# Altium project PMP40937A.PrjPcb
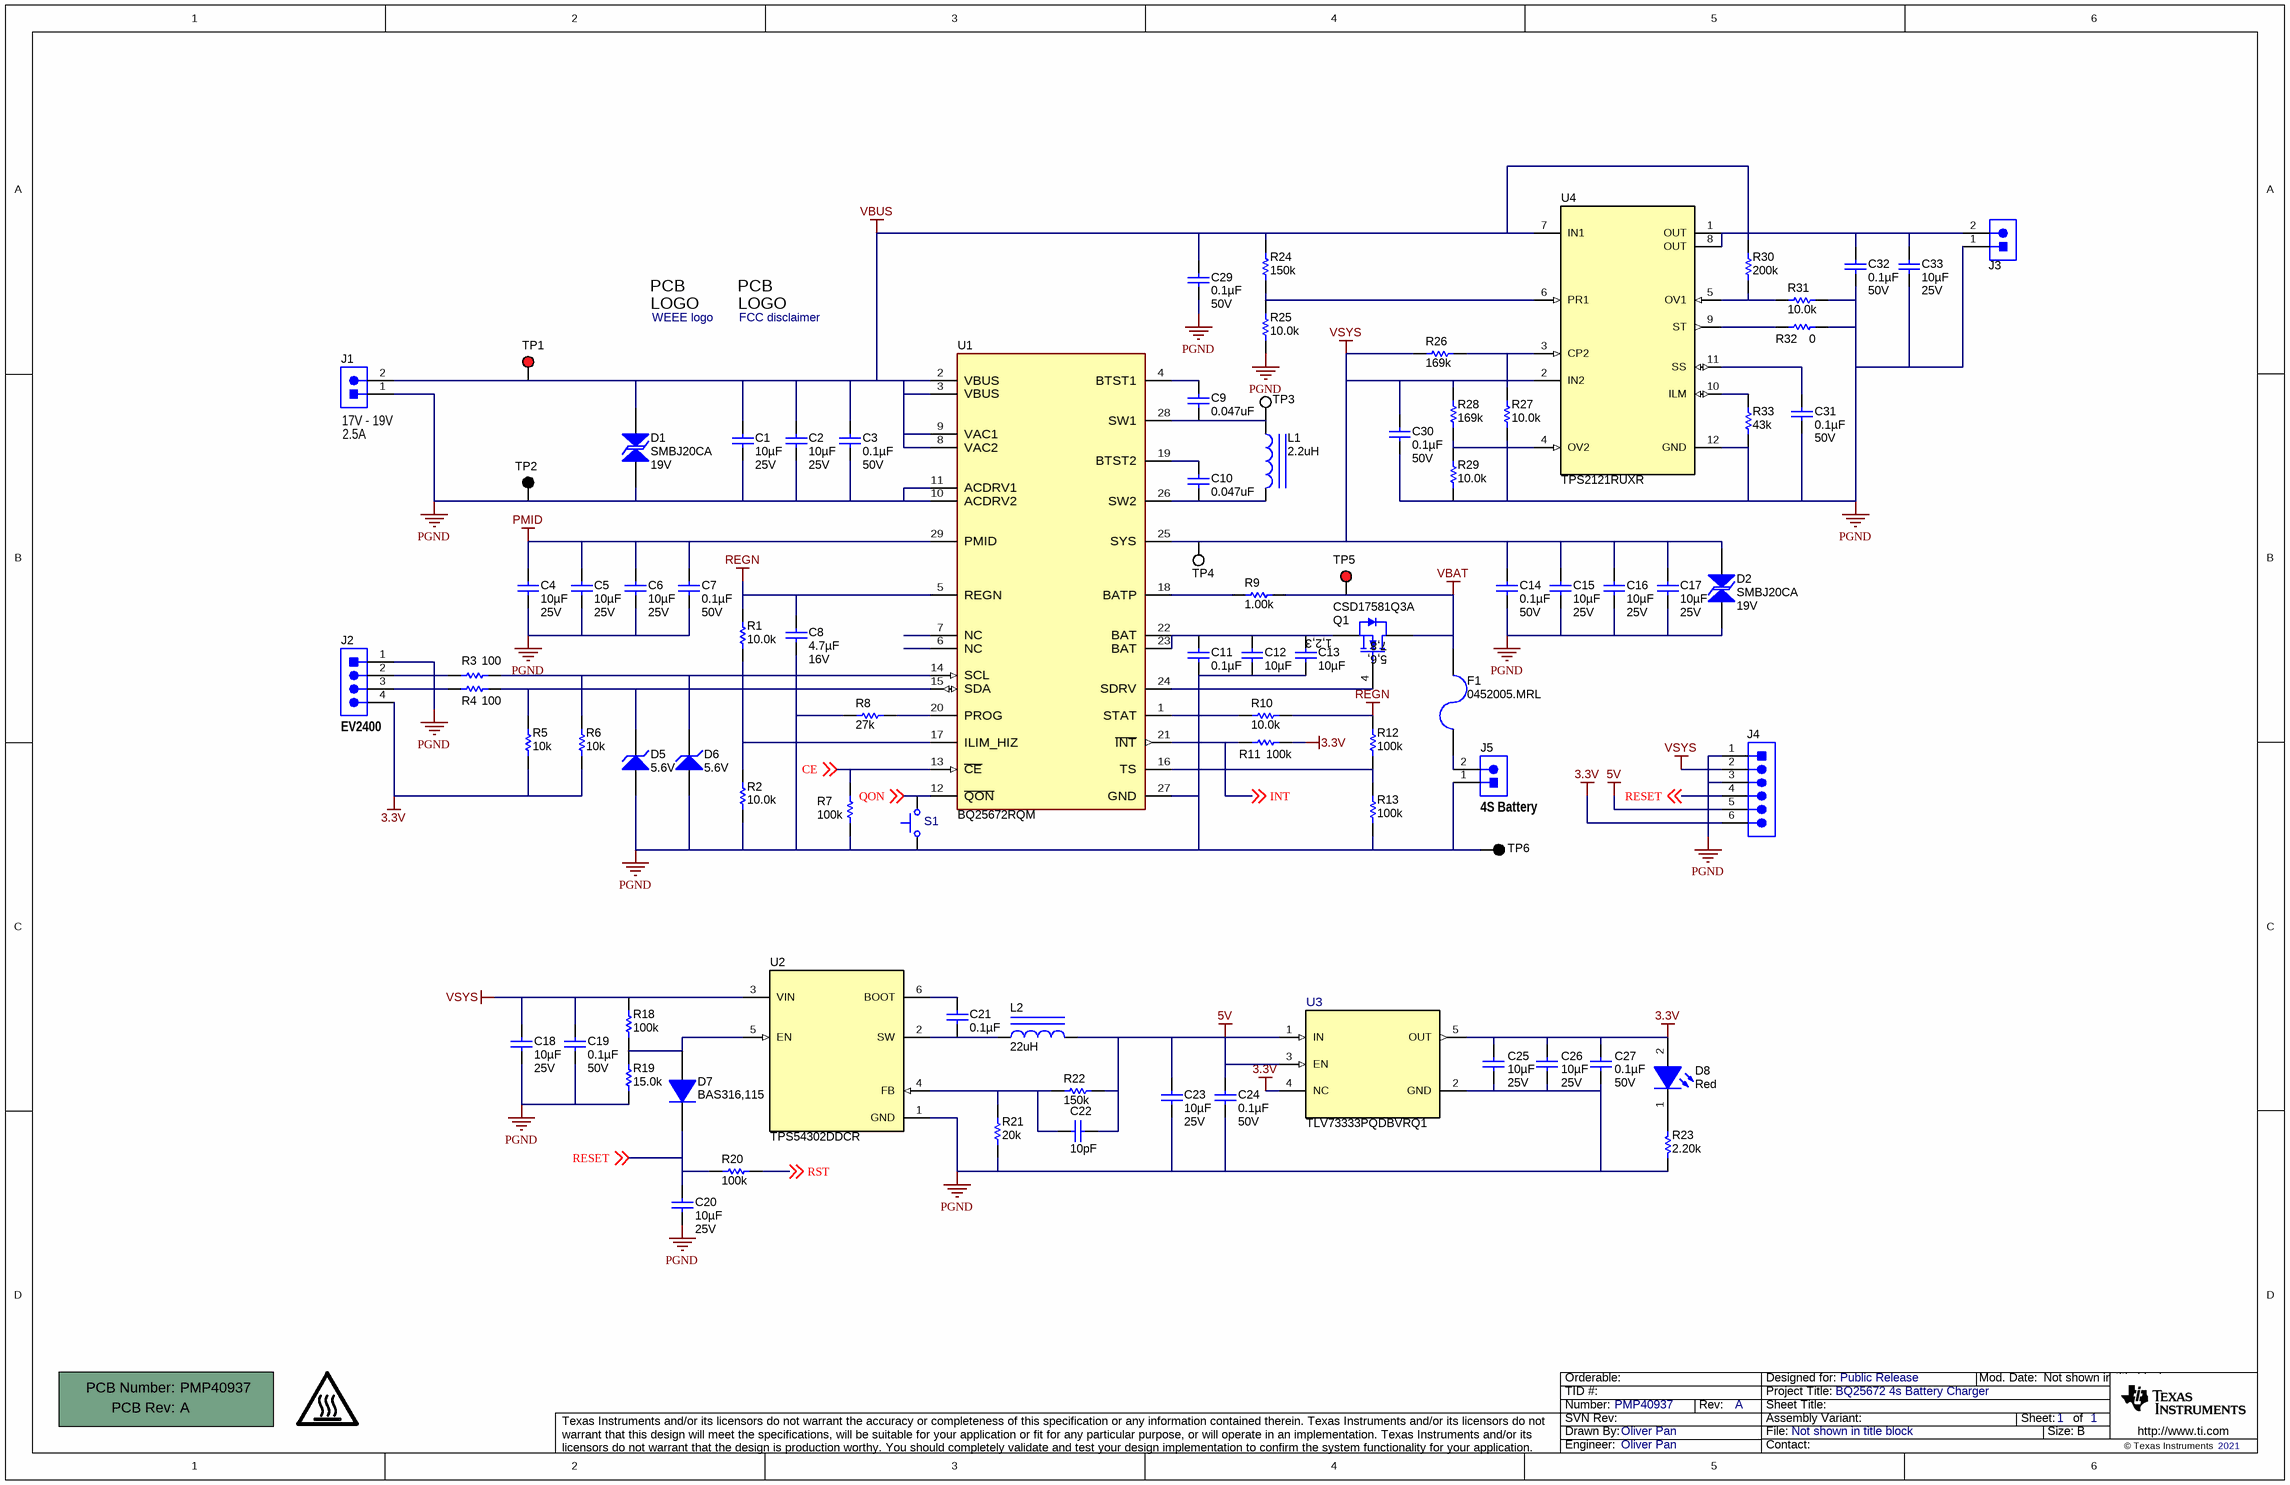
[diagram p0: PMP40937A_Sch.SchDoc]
A: http://www.ti.com/support; CopyrightYear: 2021; PCB_Layout: Oliver Pan; PCB_Rev: A; PRJ_Customer: Public Release; PRJ_Engineer: Oliver Pan; PRJ_Number: PMP40937; PRJ_Title: BQ25672 4s Battery Charger; SCH_Rev: A
1 sheet, 91 parts. Net scope: global (net labels, ports and power ports of the same name join across sheets).
Board file: PMP40937A_PCB.PcbDoc

## Sheet PMP40937A_Sch.SchDoc
size 431 x 279 mm; Date: Not shown in title block; ApprovedBy: Not shown in title block; CheckedBy: Not shown in title block; Author: Not shown in title block; CompanyName: Not shown in title block; DrawnBy: Oliver Pan; Engineer: Not shown in title block; Organization: Not shown in title block; Address1: Not shown in title block; Address2: Not shown in title block; Address3: Not shown in title block; Address4: Not shown in title block; Revision: Use project parameter SCH_Rev; PageSetup: Record=PageOptions¦CenterHorizontal=True¦CenterVertical=True¦PrintScale=1.00¦XCorrection=1.00¦YCorrection=1.00¦PrintKind=0¦BorderSize=5000000¦LeftOffset=0¦BottomOffset=0¦Orientation=2¦PaperLength=1000¦PaperWidth=1000¦Scale=100¦PaperSource=15¦PrintQuality=600¦MediaType=1¦DitherType=10¦PaperKind=Letter¦PrintScaleMode=1; DocumentNumber: 1; SheetNumber: 1; SheetTotal: 1

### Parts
!PCB1  Printed Circuit Board  (value not drawn)  (mechanical)
C1  ValueDisplayed: 10µF  Value2: 25V  [0805]  (hidden comment: CL21A106KAFN3NE)
C2  ValueDisplayed: 10µF  Value2: 25V  [0805]  (hidden comment: CL21A106KAFN3NE)
C3  ValueDisplayed: 0.1µF  Value2: 50V  [0402L]  (hidden comment: GRM155R71H104ME14D)
C4  ValueDisplayed: 10µF  Value2: 25V  [0805]  (hidden comment: CL21A106KAFN3NE)
C5  ValueDisplayed: 10µF  Value2: 25V  [0805]  (hidden comment: CL21A106KAFN3NE)
C6  ValueDisplayed: 10µF  Value2: 25V  [0805]  (hidden comment: CL21A106KAFN3NE)
C7  ValueDisplayed: 0.1µF  Value2: 50V  [0402L]  (hidden comment: GRM155R71H104ME14D)
C8  ValueDisplayed: 4.7µF  Value2: 16V  [0603L]  (hidden comment: GRM188R61C475KAAJ)
C9  ValueDisplayed: 0.047uF  [0402L]  (hidden comment: GRM155R71E473KA88D)
C10  ValueDisplayed: 0.047uF  [0402L]  (hidden comment: GRM155R71E473KA88D)
C11  ValueDisplayed: 0.1µF  [0402L]  (hidden comment: GRM155R71H104ME14D)
C12  ValueDisplayed: 10µF  [0805]  (hidden comment: CL21A106KAFN3NE)
C13  ValueDisplayed: 10µF  [0805]  (hidden comment: CL21A106KAFN3NE)
C14  ValueDisplayed: 0.1µF  Value2: 50V  [0402L]  (hidden comment: GRM155R71H104ME14D)
C15  ValueDisplayed: 10µF  Value2: 25V  [0805]  (hidden comment: CL21A106KAFN3NE)
C16  ValueDisplayed: 10µF  Value2: 25V  [0805]  (hidden comment: CL21A106KAFN3NE)
C17  ValueDisplayed: 10µF  Value2: 25V  [0805]  (hidden comment: CL21A106KAFN3NE)
C18  ValueDisplayed: 10µF  Value2: 25V  [0603L]  (hidden comment: GRM188R61E106MA73D)
C19  ValueDisplayed: 0.1µF  Value2: 50V  [0402L]  (hidden comment: GRM155R71H104ME14D)
C20  ValueDisplayed: 10µF  Value2: 25V  [0603L]  (hidden comment: GRM188R61E106MA73D)
C21  ValueDisplayed: 0.1µF  [0402L]  (hidden comment: GRM155R71H104ME14D)
C22  ValueDisplayed: 10pF  [0402L]  (hidden comment: GRM1555C1H100FA01D)
C23  ValueDisplayed: 10µF  Value2: 25V  [0603L]  (hidden comment: GRM188R61E106MA73D)
C24  ValueDisplayed: 0.1µF  Value2: 50V  [0402L]  (hidden comment: GRM155R71H104ME14D)
C25  ValueDisplayed: 10µF  Value2: 25V  [0603L]  (hidden comment: GRM188R61E106MA73D)
C26  ValueDisplayed: 10µF  Value2: 25V  [0603L]  (hidden comment: GRM188R61E106MA73D)
C27  ValueDisplayed: 0.1µF  Value2: 50V  [0402L]  (hidden comment: GRM155R71H104ME14D)
C29  ValueDisplayed: 0.1µF  Value2: 50V  [0402L]  (hidden comment: GRM155R71H104ME14D)
C30  ValueDisplayed: 0.1µF  Value2: 50V  [0402L]  (hidden comment: GRM155R71H104ME14D)
C31  ValueDisplayed: 0.1µF  Value2: 50V  [0402L]  (hidden comment: GRM155R71H104ME14D)
C32  ValueDisplayed: 0.1µF  Value2: 50V  [0402L]  (hidden comment: GRM155R71H104ME14D)
C33  ValueDisplayed: 10µF  Value2: 25V  [0805]  (hidden comment: CL21A106KAFN3NE)
D1  SMBJ20CA  value 19V  [SMB]
D2  SMBJ20CA  value 19V  [SMB]
D5  value 5.6V  [SOD-523]  (hidden comment: BZT52C5V6T-7)
D6  value 5.6V  [SOD-523]  (hidden comment: BZT52C5V6T-7)
D7  BAS316,115  [SOD-323]
D8  value Red  [WL-SMCW_RED]  (hidden comment: 150060RS75000)
F1  0452005.MRL  [SloBlo452]
J1  B2B-XH-A(LF)(SN)  [JST_B2B-XH-A]  (value not drawn)
J2  61300411121  [WURTH_61300411121]  (value not drawn)
J3  B2B-XH-A(LF)(SN)  [JST_B2B-XH-A]  (value not drawn)
J4  61300611121  [WURTH_61300611121]  (value not drawn)
J5  B2B-XH-A(LF)(SN)  [JST_B2B-XH-A]  (value not drawn)
L1  ValueDisplayed: 2.2uH  [SPM6530]  (hidden comment: SPM6530T-2R2M)
L2  ValueDisplayed: 22uH  [WE-LHMI_7030]  (hidden comment: 74437346220)
Logo1  WEEE logo  [WEEE_Minimum]  (no BOM)
Logo2  FCC disclaimer  [FCC_disclaimer]  (no BOM)
LOGO3  CAUTION HOT SURFACE  [IEC_HotSurface_Small]  (value not drawn)  (no BOM)
Q1  CSD17581Q3A  [DNH0008A]
R1  ValueDisplayed: 10.0k  [0402L]  (hidden comment: CRCW040210K0FKED)
R2  ValueDisplayed: 10.0k  [0402L]  (hidden comment: CRCW040210K0FKED)
R3  ValueDisplayed: 100  [0402L]  (hidden comment: RC0402FR-07100RL)
R4  ValueDisplayed: 100  [0402L]  (hidden comment: RC0402FR-07100RL)
R5  ValueDisplayed: 10k  [0402L]  (hidden comment: CRCW040210K0JNED)
R6  ValueDisplayed: 10k  [0402L]  (hidden comment: CRCW040210K0JNED)
R7  ValueDisplayed: 100k  [0402L]  (hidden comment: RC0402FR-07100KL)
R8  ValueDisplayed: 27k  [0402L]  (hidden comment: CRCW040227K0JNED)
R9  ValueDisplayed: 1.00k  [0402L]  (hidden comment: RC0402FR-071KL)
R10  ValueDisplayed: 10.0k  [0402L]  (hidden comment: CRCW040210K0FKED)
R11  ValueDisplayed: 100k  [0402L]  (hidden comment: RC0402FR-07100KL)
R12  ValueDisplayed: 100k  [0402L]  (hidden comment: CRCW0402100KFKED)
R13  ValueDisplayed: 100k  [0402L]  (hidden comment: CRCW0402100KFKED)
R18  ValueDisplayed: 100k  [0402L]  (hidden comment: CRCW0402100KFKED)
R19  ValueDisplayed: 15.0k  [0402L]  (hidden comment: CRCW040215K0FKED)
R20  ValueDisplayed: 100k  [0402L]  (hidden comment: RC0402FR-07100KL)
R21  ValueDisplayed: 20k  [0402L]  (hidden comment: CRCW040220K0JNED)
R22  ValueDisplayed: 150k  [0402L]  (hidden comment: CRCW0402150KFKED)
R23  ValueDisplayed: 2.20k  [0402L]  (hidden comment: RC0402FR-072K2L)
R24  ValueDisplayed: 150k  [0402L]  (hidden comment: CRCW0402150KFKED)
R25  ValueDisplayed: 10.0k  [0402L]  (hidden comment: CRCW040210K0FKED)
R26  ValueDisplayed: 169k  [0402L]  (hidden comment: CRCW0402169KFKED)
R27  ValueDisplayed: 10.0k  [0402L]  (hidden comment: CRCW040210K0FKED)
R28  ValueDisplayed: 169k  [0402L]  (hidden comment: CRCW0402169KFKED)
R29  ValueDisplayed: 10.0k  [0402L]  (hidden comment: CRCW040210K0FKED)
R30  ValueDisplayed: 200k  [0402L]  (hidden comment: CRCW0402200KFKED)
R31  ValueDisplayed: 10.0k  [0402L]  (hidden comment: CRCW040210K0FKED)
R32  ValueDisplayed: 0  [0402L]  (hidden comment: CRCW04020000Z0ED)
R33  ValueDisplayed: 43k  [0402L]  (hidden comment: CRCW040243K0JNED)
S1  B3U-1100P  [SW_B3U-1000P]  (value not drawn)
TP1  5010  [Keystone5010]  (value not drawn)
TP2  5011  [Keystone5011]  (value not drawn)
TP3  5002  [Keystone5002]  (value not drawn)
TP4  5002  [Keystone5002]  (value not drawn)
TP5  5000  [Keystone5000]  (value not drawn)
TP6  5011  [Keystone5011]  (value not drawn)
U1  BQ25672RQM  [RQM0029A-MFG]
U2  TPS54302DDCR  [DDC0006A_N]
U3  TLV73333PQDBVRQ1  [DBV0005A_N]
U4  TPS2121RUXR  [RUX0012A]

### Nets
3.3V: C25.1 C26.1 C27.2 D8.2(A) J2.4 J4.6 R5.1 R6.1 R11.1 U3.4(NC) U3.5(OUT)
5V: C22.1 C23.1 C24.2 J4.5 L2.2 R22.1 U3.1(IN) U3.3(EN)
PGND: C1.2 C2.2 C3.1 C4.2 C5.2 C6.2 C7.1 C8.1 C11.1 C12.2 C13.2 C14.1 C15.2 C16.2 C17.2 C18.2 C19.1 C20.2 C23.2 C24.1 C25.2 C26.2 C27.1 C29.1 C30.1 C31.1 C32.1 C33.2 D1.2 D2.2 D5.2(A) D6.2(A) J1.1 J2.1 J3.1 J4.1 J4.3 J5.1 R2.1 R7.2 R8.2 R13.1 R19.1 R21.1 R23.2 R25.2 R27.2 R29.1 R31.1 R32.1 R33.1 S1.1 TP2.1 TP6.1 U1.10(ACDRV2) U1.11(ACDRV1) U1.27(GND) U2.1(GND) U3.2(GND) U4.12(GND)
PMID: C4.1 C5.1 C6.1 C7.2 U1.29(PMID)
REGN: C8.2 R1.2 R10.1 R12.2 U1.5(REGN)
VBAT: F1.2 Q1.5(D) Q1.6(D) Q1.7(D) Q1.8(D) Q1.9(D) R9.2 TP5.1
VBUS: C1.1 C2.1 C3.2 C29.2 D1.1 J1.2 R24.1 R30.1 TP1.1 U1.2(VBUS) U1.3(VBUS) U1.8(VAC2) U1.9(VAC1) U4.7(IN1)
VSYS: C14.2 C15.1 C16.1 C17.1 C18.1 C19.2 C30.2 D2.1 J4.2 R18.2 R26.1 R28.2 TP4.1 U1.25(SYS) U2.3(VIN) U4.2(IN2)
CE: R7.1 U1.13(~{CE}) ; off-sheet CE
INT: R11.2 U1.21(~{INT}) ; off-sheet INT
QON: S1.2 U1.12(~{QON}) ; off-sheet QON
RESET: C20.1 D7.1(K) J4.4 R20.2 ; off-sheet RESET
RST: R20.1 ; off-sheet RST
NetC9_1: C9.1 L1.2 TP3.1 U1.28(SW1)
NetC9_2: C9.2 U1.4(BTST1)
NetC10_1: C10.1 L1.1 U1.26(SW2)
NetC10_2: C10.2 U1.19(BTST2)
NetC11_2: C11.2 C12.1 C13.1 Q1.1(S) Q1.2(S) Q1.3(S) U1.22(BAT) U1.23(BAT)
NetC21_1: C21.1 L2.1 U2.2(SW)
NetC21_2: C21.2 U2.6(BOOT)
NetC22_2: C22.2 R21.2 R22.2 U2.4(FB)
NetC31_2: C31.2 U4.11(SS)
NetC32_2: C32.2 C33.1 J3.2 U4.1(OUT) U4.8(OUT)
NetD5_1: D5.1(K) R4.2 R5.2 U1.15(SDA)
NetD6_1: D6.1(K) R3.2 R6.2 U1.14(SCL)
NetD7_2: D7.2(A) R18.1 R19.2 U2.5(EN)
NetD8_1: D8.1(K) R23.1
NetF1_1: F1.1 J5.2
NetJ2_2: J2.2 R3.1
NetJ2_3: J2.3 R4.1
NetQ1_4: Q1.4(G) U1.24(SDRV)
NetR1_1: R1.1 R2.2 U1.17(ILIM_HIZ)
NetR8_1: R8.1 U1.20(PROG)
NetR9_1: R9.1 U1.18(BATP)
NetR10_2: R10.2 U1.1(STAT)
NetR12_1: R12.1 R13.2 U1.16(TS)
NetR24_2: R24.2 R25.1 U4.6(PR1)
NetR26_2: R26.2 R27.1 U4.3(CP2)
NetR28_1: R28.1 R29.2 U4.4(OV2)
NetR30_2: R30.2 R31.2 U4.5(OV1)
NetR32_2: R32.2 U4.9(ST)
NetR33_2: R33.2 U4.10(ILM)

Not connected (* = marked no-connect by the designer): U1 6(NC) 7(NC)

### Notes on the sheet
- (near J1) 2.5A
- (near J1) 17V - 19V
- (near J2) EV2400
- (near J5) 4S Battery
- (near S1) 1. Adapter Voltage:17V-19V
  2. Battery Voltage: 4S battery with 16.8V maximum regulation voltage
  3. Maximum charging current: 2.5A
  4. ESD protection: 15kV IEC61000-4-2 protection. Striking in adapter port when the charger is operating.
  5. Power on/off requirement: Need to achieve whole system power on/off without adding any external components.
  6. Whole system reset with button: Need whole system reset if customer press power on button for a long time (10s)
  7. Need to totally disconnect all system load to reduce battery leakage.
  8. Design with two layer board to optimized cost and achieve small size solution. (target 3.5cmx3.5cm)

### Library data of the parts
!PCB1 = CMP-0003618-2: Manufacturer: Any; PartNumber: PMP40937
C1 C2 C4-C6 C15-C17 C33 = CL21A106KAFN3NE: CAP, CERM, 10 µF, 25 V,+/- 10%, X5R, 0805; Manufacturer: Samsung Electro-Mechanics; Polarized: N; CompType: Capacitor; Value: 10uF; U/M: EA; Cap_F: 0.00001; Tolerance_%: 10; VDC_V: 25; TaMin_C: -55; TaMax_C: 85; SizeArea_mm2: 2.5; SizeAreaWB_mm2: 6.75; SizeX_mm: 2; SizeY_mm: 1.25; SizeZ_mm: 1.45; AEC Category: Q200; Green_Lifecycle: Active; Green_REACh: Passed
C3 C7 C14 C19 C24 C27 C29-C32 = GRM155R71H104ME14D: CAP, CERM, 0.1 µF, 50 V,+/- 20%, X7R, 0402; Manufacturer: MuRata; Polarized: N; CompType: Capacitor; Value: 0.1uF; U/M: EA; Cap_F: 0.0000001; Tolerance_%: 20; VDC_V: 50; TaMin_C: -55; TaMax_C: 125; Cap_Case: 0402; SizeArea_mm2: 0.5; SizeAreaWB_mm2: 3; SizeX_mm: 1; SizeZ_mm: 0.6; AEC Category: Q200
C8 = GRM188R61C475KAAJ: CAP, CERM, 4.7 µF, 16 V,+/- 10%, X5R, 0603; Manufacturer: MuRata; Polarized: N; CompType: Capacitor; Value: 4.7uF; U/M: EA; Cap_F: 0.0000047; Tolerance_%: 10; VDC_V: 16; TaMin_C: -55; TaMax_C: 85; Cap_Case: 0603; SizeArea_mm2: 1.28; SizeAreaWB_mm2: 4.68; SizeX_mm: 1.6; SizeY_mm: 0.8; SizeZ_mm: 1; AEC Category: Q200; Green_Lifecycle: Active; Green_REACh: Passed
C9 C10 = CMP-0006669-2: CAP, CERM, 0.047 uF, 25 V, +/- 10%, X7R, 0402; Manufacturer: MuRata; Polarized: N; U/M: EA; Cap_F: 47nF; Value1: Unknown; VDC_V: 25V; TaMin_C: -55°C; TaMax_C: 125°C; Cap_Case: 0402; AEC Category: Q200; SizeArea_mm2: 0.5; SizeAreaWB_mm2: 3; SizeX_mm: 1; SizeZ_mm: 0.6
C11 C21 = GRM155R71H104ME14D: CAP, CERM, 0.1 µF, 50 V,+/- 20%, X7R, 0402; Manufacturer: MuRata; Polarized: N; CompType: Capacitor; Value: 0.1uF; U/M: EA; Cap_F: 0.0000001; Tolerance_%: 20; VDC_V: 50; Value2: 50V; TaMin_C: -55; TaMax_C: 125; Cap_Case: 0402; SizeArea_mm2: 0.5; SizeAreaWB_mm2: 3; SizeX_mm: 1; SizeZ_mm: 0.6; AEC Category: Q200
C12 C13 = CL21A106KAFN3NE: CAP, CERM, 10 µF, 25 V,+/- 10%, X5R, 0805; Manufacturer: Samsung Electro-Mechanics; Polarized: N; CompType: Capacitor; Value: 10uF; U/M: EA; Cap_F: 0.00001; Tolerance_%: 10; VDC_V: 25; Value2: 25V; TaMin_C: -55; TaMax_C: 85; SizeArea_mm2: 2.5; SizeAreaWB_mm2: 6.75; SizeX_mm: 2; SizeY_mm: 1.25; SizeZ_mm: 1.45; AEC Category: Q200; Green_Lifecycle: Active; Green_REACh: Passed
C18 C20 C23 C25 C26 = GRM188R61E106MA73D: CAP, CERM, 10 µF, 25 V,+/- 20%, X5R, 0603; Manufacturer: MuRata; Polarized: N; CompType: Capacitor; Value: 10uF; U/M: EA; Cap_F: 0.00001; Tolerance_%: 20; VDC_V: 25; TaMin_C: -55; TaMax_C: 85; Cap_Case: 0603; SizeArea_mm2: 1.28; SizeAreaWB_mm2: 4.68; SizeX_mm: 1.6; SizeY_mm: 0.8; SizeZ_mm: 1; AEC Category: Q200; Green_Lifecycle: Active; Green_REACh: Passed
C22 = GRM1555C1H100FA01D: CAP, CERM, 10 pF, 50 V,+/- 1%, C0G/NP0, 0402; Manufacturer: MuRata; Polarized: N; CompType: Capacitor; Value: 10pF; U/M: EA; Cap_F: 0.00000000001; Tolerance_%: 1; VDC_V: 50; Value2: 50V; TaMin_C: -55; TaMax_C: 125; Cap_Case: 0402; SizeArea_mm2: 0.5; SizeAreaWB_mm2: 3; SizeZ_mm: 0.6; AEC Category: Q200
D1 D2 = SMBJ20CA: Diode, TVS, Bi, 19 V, SMB; Manufacturer: Littelfuse; U/M: EA; Power_W: 5; Vr_V: 19; Value1: 5W; RJA_CperW: 100; SizeAreaWB_mm2: 44.156; SizeArea_mm2: 21.336; SizeX_mm: 5.6; SizeY_mm: 3.81; SizeZ_mm: 2.6; AEC Category: Q101
D5 D6 = BZT52C5V6T-7: Diode, Zener, 5.6 V, 300 mW, SOD-523; Manufacturer: Diodes Inc.; SymbolCreator: a0412235; U/M: EA; Power_W: 0.3; Vz_V: 5.6; Value1: 0.3W; RJA_CperW: 417; SizeAreaWB_mm2: 5.13; SizeArea_mm2: 1.53; SizeX_mm: 1.7; SizeY_mm: 0.9; SizeZ_mm: 0.65; AEC Category: Q101; Green_Lifecycle: Active; Green_REACh: Passed
D7 = BAS316,115: Diode, Ultrafast, 100 V, 0.25 A, SOD-323; Manufacturer: Nexperia; U/M: EA; Vf_V: 1.4; Value: 100V; Value1: 0.25A; Value2: 1.4V; Io_A: 0.25; Vr_V: 100; TJmax_C: 150; SizeAreaWB_mm2: 8.695; SizeArea_mm2: 3.645; SizeX_mm: 2.7; SizeY_mm: 1.35; SizeZ_mm: 1; AEC Category: Q101; Green_Lifecycle: Not Set; Green_REACh: Incomplete
D8 = 150060RS75000: LED, Red, SMD; Manufacturer: Wurth Elektronik; Type: AlInGaP; Vf_V: 2; Value2: 2V; Io_A: 0.03; Vr_V: 5; Tjmax_C: 85; Power_TotalModule: 0.072; Value1: 0.072W; Angle: 140; U/M: EA; Green_Lifecycle: Active; Green_REACh: Passed
F1 = 0452005.MRL: Fuse, 5 A, 125VAC/VDC, SMD; Manufacturer: Littelfuse; VDC_V: 125; Interrupt_DC: 50; Irating_A: 5; Rtyp_Ohm: 0.0136; MeltingTyp: 53.72
J1 J3 J5 = CMP-0075223-1: Header (Shrouded), 2.5mm, 2x1, Tin, TH; Manufacturer: JST Manufacturing; CNHeader: False; Current_A: 3A; Shrouded: Y; Gender: Male; Voltage_V: 250V; Row_Count: 1; Pitch_mm: 2.5
J2 = 61300411121: Header, 2.54 mm, 4x1, Gold, TH; Manufacturer: Wurth Elektronik; SymbolCreator: a0412235
J4 = 61300611121: Header, 2.54 mm, 6x1, Gold, TH; Manufacturer: Wurth Elektronik; SymbolCreator: a0412235
L1 = CMP-0062870-1: Inductor, Shielded, Ferrite, 2.2 uH, 8.2 A, 0.019 ohm, SMD; Manufacturer: TDK; Isat: 8.4A @ 20% inductance drop; Irms: 8.2A @ 40C rise; Green_Lifecycle: Active; SizeAreaWB_mm2: 77.35; DCR_ohm: 19m; Green_REACh: Passed; Value: 2.2uH; Imax_A: 8.2A; SizeZ_mm: 3; SizeX_mm: 7.1; SizeY_mm: 6.5; SizeArea_mm2: 46.15; Ind_H: 2.2µH; AEC Category: Q200
L2 = CMP-0064490-2: Inductor, Shielded Drum Core, Powdered Iron, 22 uH, 1.9 A, 0.165 ohm, SMD; Manufacturer: Wurth Elektronik; Isat: 4.5A @ 20% inductance drop; Irms: 1.9A @ 40C rise; Green_Lifecycle: Active; SizeAreaWB_mm2: 73.96; DCR_ohm: 1.65d; Green_REACh: Passed; Value: 22uH; Imax_A: 1.9A; SizeZ_mm: 3; SizeX_mm: 6.6; SizeArea_mm2: 43.56; Ind_H: 22µH; AEC Qualified: N; AEC Category: Q200
Logo1 = CMP-0074769-1
Logo2 = CMP-0074847-1: FCC_disclaimer; Library Reference: Logo
LOGO3 = CMP-0074837-1: IEC 61010-1 Hot Surface Warning; Library Reference: IEC_HotSurface; SymbolCreator: a0412235
Q1 = CMP-0079500-2: MOSFET, N-CH, 30 V, 60 A, DNH0008A (VSONP-8); Manufacturer: Texas Instruments; Alternate Manufacturer: None; ChType: N; QgTyp_nC: 20; SizeAreaWB_mm2: 18.49; SizeArea_mm2: 10.89; IdsMax_A: 60A; VdsMax_V: 30V; Rdson45_ohm: 4.7m; Vgs_V: 20V; AEC Category: Q101; Value: 30V; SizeZ_mm: 0.9; SizeY_mm: 3.3; Value2: 20 nC; Value1: 0.0047 ohm; ChMode: Enhancement
R1 R2 R10 R25 R27 R29 R31 = CRCW040210K0FKED: RES, 10.0 k, 1%, 0.063 W, 0402; Manufacturer: Vishay-Dale; CompType: Resistor; Value: 10.0k; Res_ohm: 10000; Value_Code: 10k0; Tolerance_%: 1; Power_W: 0.063; Value2: 0.063W; VDC_V: 50; TempCo: 100 ppm/C; SizeArea_mm2: 0.5; SizeZ_mm: 0.6; EIA_Code: E96; U/M: EA; AEC Category: Q200; Green_Lifecycle: Active; Green_REACh: Passed
R3 R4 = RC0402FR-07100RL: RES, 100, 1%, 0.063 W, 0402; Manufacturer: Yageo America; CompType: Resistor; Value: 100; Value_Code: 100R; Tolerance_%: 1; Power_W: 0.063; Value2: 0.063W; VDC_V: 50; TempCo: 100 ppm/C; SizeArea_mm2: 0.5; SizeZ_mm: 0.6; EIA_Code: E96; U/M: EA; AEC Category: Q200; AEC Qualified: N; Green_Lifecycle: Active; Green_REACh: Passed
R5 R6 = CRCW040210K0JNED: RES, 10 k, 5%, 0.063 W, 0402; Manufacturer: Vishay-Dale; CompType: Resistor; Value: 10k; Res_ohm: 10000; Value_Code: 10k0; Tolerance_%: 5; Power_W: 0.063; Value2: 0.063W; VDC_V: 50; TempCo: 200 ppm/C; SizeArea_mm2: 0.5; SizeX_mm: 1; SizeZ_mm: 0.6; EIA_Code: E24; U/M: EA; AEC Category: Q200; Green_Lifecycle: Active; Green_REACh: Passed
R7 R11 = RC0402FR-07100KL: RES, 100 k, 1%, 0.0625 W, 0402; Manufacturer: Yageo America; CompType: Resistor; Value: 100k; Res_ohm: 100000; Tolerance_%: 1; Power_W: 0.0625; VDC_V: 50; TempCo: 100 ppm/C; SizeArea_mm2: 0.5; SizeZ_mm: 0.6; EIA_Code: E96; U/M: EA; AEC Category: Q200; AEC Qualified: N; Green_Lifecycle: Active; Green_REACh: Passed
R8 = CRCW040227K0JNED: RES, 27 k, 5%, 0.063 W, 0402; Manufacturer: Vishay-Dale; CompType: Resistor; Value: 27k; Res_ohm: 27000; Value_Code: 27k0; Tolerance_%: 5; Power_W: 0.063; Value2: 0.063W; VDC_V: 50; TempCo: 200 ppm/C; SizeArea_mm2: 0.5; SizeX_mm: 1; SizeZ_mm: 0.6; EIA_Code: E24; U/M: EA; AEC Category: Q200; Green_Lifecycle: Active; Green_REACh: Passed
R9 = RC0402FR-071KL: RES, 1.00 k, 1%, 0.0625 W, 0402; Manufacturer: Yageo America; CompType: Resistor; Value: 1.00k; Res_ohm: 1000; Value_Code: 1k00; Tolerance_%: 1; Power_W: 0.0625; VDC_V: 50; TempCo: 100 ppm/C; SizeArea_mm2: 0.5; SizeZ_mm: 0.6; EIA_Code: E96; U/M: EA; AEC Category: Q200; AEC Qualified: N; Green_Lifecycle: Active; Green_REACh: Passed
R12 R13 R18 = CRCW0402100KFKED: RES, 100 k, 1%, 0.063 W, 0402; Manufacturer: Vishay-Dale; CompType: Resistor; Value: 100k; Res_ohm: 100000; Tolerance_%: 1; Power_W: 0.063; Value2: 0.063W; VDC_V: 50; TempCo: 100 ppm/C; SizeArea_mm2: 0.5; SizeZ_mm: 0.6; EIA_Code: E96; U/M: EA; AEC Category: Q200; Green_Lifecycle: Active; Green_REACh: Passed
R19 = CRCW040215K0FKED: RES, 15.0 k, 1%, 0.063 W, 0402; Manufacturer: Vishay-Dale; CompType: Resistor; Value: 15.0k; Res_ohm: 15000; Value_Code: 15k0; Tolerance_%: 1; Power_W: 0.063; Value2: 0.063W; VDC_V: 50; TempCo: 100 ppm/C; SizeArea_mm2: 0.5; SizeZ_mm: 0.6; EIA_Code: E96; U/M: EA; AEC Category: Q200; Green_Lifecycle: Active; Green_REACh: Passed
R20 = CMP-0026721-1: RES, 100 k, 1%, 0.0625 W, 0402; Manufacturer: Yageo America; Power_W: 62.5mW; TempCo: 100 ppm/C; U/M: EA; Value: 100k; EIA_Code: E96; SizeX_mm: 1; SizeY_mm: 0.5; SizeZ_mm: 0.6; AEC Qualified: N; VDC_V: 50V; AEC Category: Q200
R21 = CRCW040220K0JNED: RES, 20 k, 5%, 0.063 W, 0402; Manufacturer: Vishay-Dale; CompType: Resistor; Value: 20k; Res_ohm: 20000; Value_Code: 20k0; Tolerance_%: 5; Power_W: 0.063; Value2: 0.063W; VDC_V: 50; TempCo: 200 ppm/C; SizeArea_mm2: 0.5; SizeX_mm: 1; SizeZ_mm: 0.6; EIA_Code: E24; U/M: EA; AEC Category: Q200; Green_Lifecycle: Active; Green_REACh: Passed
R22 R24 = CRCW0402150KFKED: RES, 150 k, 1%, 0.063 W, 0402; Manufacturer: Vishay-Dale; CompType: Resistor; Value: 150k; Res_ohm: 150000; Tolerance_%: 1; Power_W: 0.063; Value2: 0.063W; VDC_V: 50; TempCo: 100 ppm/C; SizeArea_mm2: 0.5; SizeZ_mm: 0.6; EIA_Code: E96; U/M: EA; AEC Category: Q200; Green_Lifecycle: Active; Green_REACh: Passed
R23 = RC0402FR-072K2L: RES, 2.20 k, 1%, 0.063 W, 0402; Manufacturer: Yageo America; CompType: Resistor; Value: 2.20k; Res_ohm: 2200; Value_Code: 2k20; Tolerance_%: 1; Power_W: 0.063; Value2: 0.063W; TempCo: 100 ppm/C; SizeArea_mm2: 0.5; SizeZ_mm: 0.6; U/M: EA; AEC Category: Q200; AEC Qualified: N; Green_Lifecycle: Active; Green_REACh: Passed
R26 R28 = CRCW0402169KFKED: RES, 169 k, 1%, 0.063 W, 0402; Manufacturer: Vishay-Dale; CompType: Resistor; Value: 169k; Res_ohm: 169000; Tolerance_%: 1; Power_W: 0.063; Value2: 0.063W; VDC_V: 50; TempCo: 100 ppm/C; SizeArea_mm2: 0.5; SizeZ_mm: 0.6; EIA_Code: E96; U/M: EA; AEC Category: Q200
R30 = CRCW0402200KFKED: RES, 200 k, 1%, 0.063 W, 0402; Manufacturer: Vishay-Dale; CompType: Resistor; Value: 200k; Res_ohm: 200000; Tolerance_%: 1; Power_W: 0.063; Value2: 0.063W; VDC_V: 50; TempCo: 100 ppm/C; SizeArea_mm2: 0.5; SizeZ_mm: 0.6; EIA_Code: E96; U/M: EA; AEC Category: Q200; Green_Lifecycle: Active; Green_REACh: Passed
R32 = CRCW04020000Z0ED: RES, 0, 5%, 0.063 W, 0402; Manufacturer: Vishay-Dale; CompType: Resistor; Value: 0; Value_Code: 0000; Tolerance_%: 5; Power_W: 0.063; Value2: 0.063W; VDC_V: 50; TempCo: 200 ppm/C; SizeArea_mm2: 0.5; SizeX_mm: 1; SizeZ_mm: 0.6; EIA_Code: E24; U/M: EA; AEC Category: Q200; Green_Lifecycle: Active; Green_REACh: Passed
R33 = CRCW040243K0JNED: RES, 43 k, 5%, 0.063 W, 0402; Manufacturer: Vishay-Dale; CompType: Resistor; Value: 43k; Res_ohm: 43000; Value_Code: 43k0; Tolerance_%: 5; Power_W: 0.063; Value2: 0.063W; VDC_V: 50; TempCo: 200 ppm/C; SizeArea_mm2: 0.5; SizeX_mm: 1; SizeZ_mm: 0.6; EIA_Code: E24; U/M: EA; AEC Category: Q200
S1 = KSR221GLFS: Switch, Normally open, 2.3N force, 200k operations, SMD; Circuit: SPST Switch; VDC_V: 32; SwitchFunction: Off-Mom; PositionCount: 1; CurrentRating_mA: 1001; Green_Lifecycle: Active; Green_REACh: Passed
TP1 = 5010: Test Point, Multipurpose, Red, TH; Manufacturer: Keystone; CompType: Test Point Loop; ContactFinish: Silver; Green_Lifecycle: Active; Green_REACh: Passed
TP2 TP6 = 5011: Test Point, Multipurpose, Black, TH; Manufacturer: Keystone; CompType: Test Point Loop; ContactFinish: Silver; Green_Lifecycle: Active; Green_REACh: Passed
TP3 TP4 = CMP-0055139-1: Test Point, Miniature, White, TH; Manufacturer: Keystone; CNHeader: FALSE; ContactFinish: Silver; CT: TRUE; Green_Lifecycle: Active; Green_REACh: Passed
TP5 = 5000: Test Point, Miniature, Red, TH; Manufacturer: Keystone; CompType: Test Point Loop; ContactFinish: Silver; Green_Lifecycle: Active; Green_REACh: Passed
U1 = CMP-0091155-2: I2C Controlled, 1-4 Cell, 5-A Buck Battery Charger with Dual-Input Selector and Integrated ADC; Manufacturer: Texas Instruments; AEC Qualified: No; Max Supply Voltage: 24V; SizeZ_mm: 1mm; Number Of Outputs: 4; CompType: IC; Standoff Height: 0mm; AEC Category: Q200; Min Supply Voltage: 3.6V
U2 = TPS54302DDCR: 4.5-V to 28-V Input, 3-A Output, EMI Friendly Synchronous Step-Down Converter, DDC0006A (SOT-23-T-6); Alternate PartNumber: TPS54302DDCT; Manufacturer: Texas Instruments; SymbolCreator: Altium; SizeArea_mm2: 4.8675; SizeAreaWB_mm2: 10.4675; SizeX_mm: 1.65; SizeY_mm: 2.95; SizeZ_mm: 0.87; CompType: IC; U/M: EA
U3 = CMP-0860155-1: Automotive capacitor-free 300-mA LDO regulator with foldback current limit for portable devices, DBV0005A (SOT-23-5); Manufacturer: Texas Instruments; SizeZ_mm: 1.45; SizeAreaWB_mm2: 14.82; SizeArea_mm2: 8.12; SizeY_mm: 2.9; CompType: IC; SizeX_mm: 2.8; AEC Category: Q200; AEC Qualified: Y
U4 = CMP-0078351-3: 2.7V-22V, 4A, 50mohm Priority Power MUX, RUX0012A (VQFN-HR-12); Alternate PartNumber: TPS2121RUXT; Alternate Manufacturer: Texas Instruments; SizeAreaWB_mm2: 10.5; SizeZ_mm: 1; SizeX_mm: 2; SizeY_mm: 2.5; SizeArea_mm2: 5; CompType: IC; AEC Qualified: N; AEC Category: Q200

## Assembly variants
001: not fitted C21 C29 C30 C32 C33 D2 D5 D6 R19 R24 R26; alternate parts R23 -> CMP-0086176-1, R6 -> CRCW040210K0JNED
